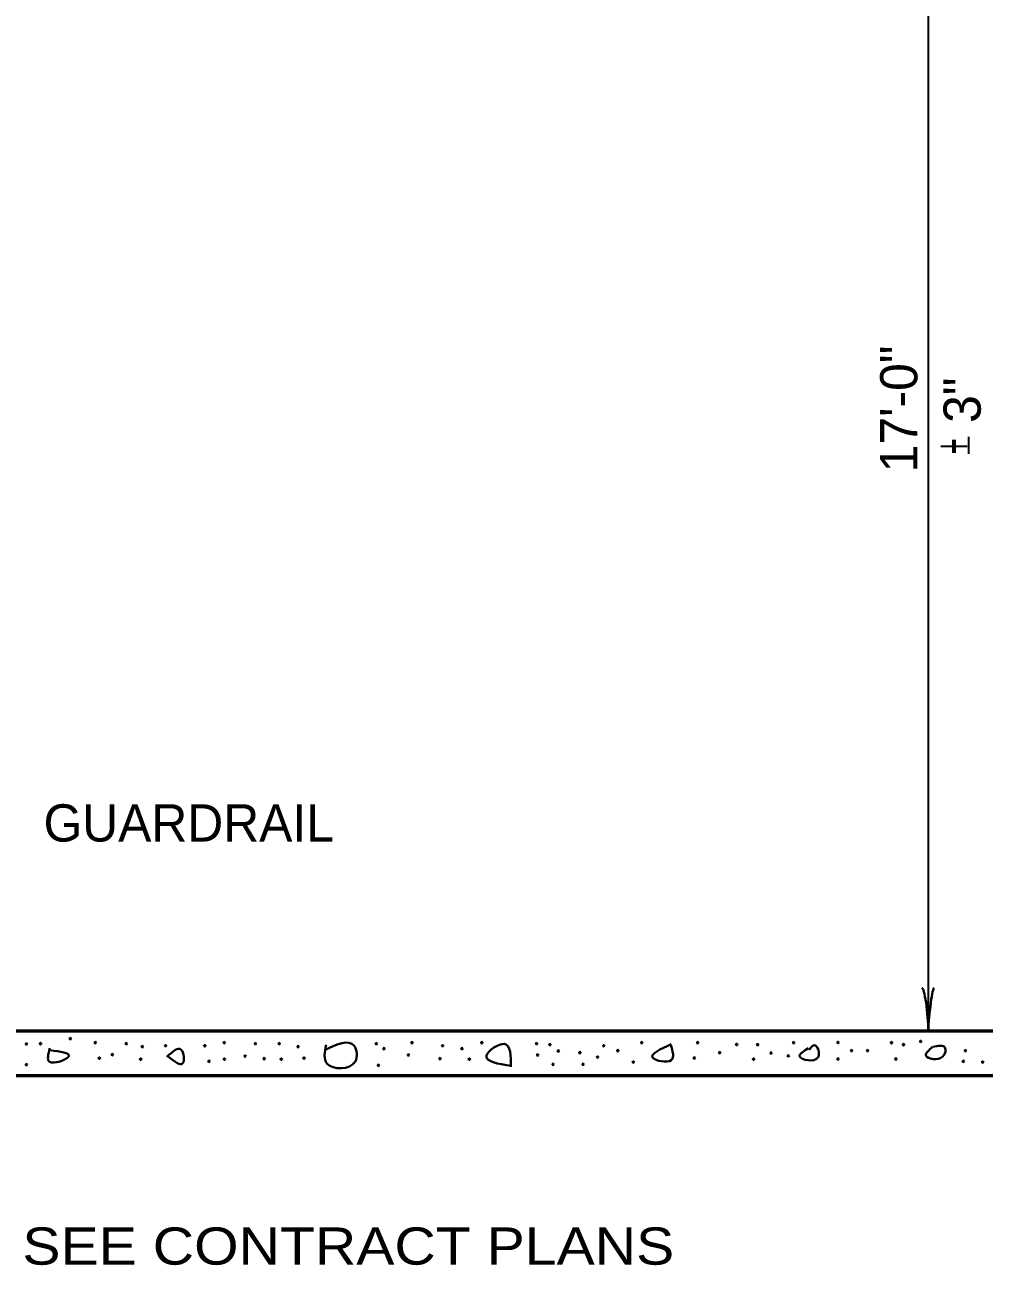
# Model space of a CAD drawing. Extents: x 12366 to 13046, y 9129 to 9570.
# Drawn here: x 12498.6 to 12563.1, y 9378.4 to 9461.7 of the extents above; entities that cross this region are included whole.
import ezdxf
from ezdxf.enums import TextEntityAlignment as Align

# ---------------------------------------------------------------- set-up
doc = ezdxf.new("R2010")
doc.units = 0
doc.layers.add('1', color=7, linetype='Continuous', lineweight=53)

msp = doc.modelspace()

# ---------------------------------------------------------------- linework, layer by layer
at = {"layer": '1', "lineweight": 35}
for p, q in [((12559.307, 9478.407), (12559.307, 9394.186)), ((12562.036, 9432.922), (12562.036, 9434.078))]:
    msp.add_line(p, q, dxfattribs=at)
at = {"layer": '1'}
for points in [[(12495.321, 9394.186), (12620.321, 9394.186), (12620.321, 9397.186), (12649.358, 9397.186)], [(12495.321, 9394.167), (12495.321, 9391.186), (12622.571, 9391.186), (12622.571, 9397.186)]]:
    msp.add_lwpolyline(points, dxfattribs=at)
at = {"layer": '1', "lineweight": 40}
for centre in [(12498.726, 9393.289), (12499.671, 9393.312), (12501.679, 9393.646), (12503.35, 9393.382), (12505.433, 9393.312), (12506.511, 9393.109), (12508.072, 9393.174), (12510.71, 9393.174), (12512.013, 9393.377), (12514.112, 9393.312), (12515.709, 9393.312), (12516.979, 9393.109), (12522.236, 9393.312), (12524.629, 9393.377), (12526.679, 9393.174), (12529.318, 9393.382), (12532.997, 9393.312), (12533.89, 9393.243), (12537.51, 9393.174), (12540.064, 9393.377), (12543.822, 9393.377), (12546.438, 9393.257), (12547.849, 9393.243), (12550.265, 9393.377), (12553.243, 9393.396), (12556.841, 9393.377), (12557.646, 9393.243), (12558.797, 9393.465), (12503.628, 9392.341), (12504.497, 9392.572), (12506.405, 9392.271), (12512.029, 9392.271), (12513.418, 9392.479), (12514.698, 9392.304), (12515.848, 9392.271), (12517.375, 9392.341), (12522.751, 9392.975), (12524.388, 9392.549), (12526.509, 9392.304), (12527.985, 9392.975), (12528.484, 9392.271), (12533.067, 9392.549), (12534.456, 9392.826), (12535.904, 9392.706), (12537.094, 9392.41), (12538.454, 9392.84), (12543.592, 9392.354), (12545.299, 9392.706), (12547.571, 9392.271), (12548.751, 9392.688), (12549.91, 9392.493), (12553.243, 9392.285), (12554.157, 9392.84), (12555.231, 9392.84), (12557.131, 9392.285), (12561.807, 9392.84), (12498.726, 9391.901), (12510.988, 9392.132), (12522.374, 9391.854), (12534.108, 9391.924), (12536.122, 9391.924), (12539.495, 9392.077), (12561.665, 9392.132), (12562.963, 9392.077)]:
    msp.add_circle(centre, 0.05, dxfattribs=at)
for centre, major_axis, ratio, start_param, end_param in [((12559.031, 9395.277), (0.156, -1.786), 0.122415, 0.896353, 3.141593), ((12559.519, 9395.307), (0.176, 1.756), 0.07063, 6.282307, 8.559703)]:
    msp.add_ellipse(centre, major_axis=major_axis, ratio=ratio, start_param=start_param, end_param=end_param, dxfattribs=at)
for points in [[(12508.155, 9392.436), (12509.128, 9392.906), (12509.229, 9392), (12508.222, 9392.469)], [(12518.858, 9393.241), (12518.926, 9391.966), (12520.805, 9392.1), (12520.737, 9393.174), (12518.791, 9392.906)], [(12531.307, 9391.815), (12529.629, 9392.52), (12530.837, 9393.292), (12531.273, 9391.748)], [(12542.044, 9393.275), (12540.802, 9392.369), (12542.044, 9392.201), (12542.01, 9393.242)], [(12551.271, 9393.007), (12550.667, 9392.47), (12551.909, 9392.403), (12551.674, 9393.208), (12551.305, 9392.906)], [(12559.593, 9393.091), (12559.156, 9392.52), (12560.297, 9392.453), (12560.431, 9393.057), (12559.626, 9393.091)], [(12500.303, 9393.006), (12500.27, 9392.1), (12501.578, 9392.469), (12500.303, 9392.872)]]:
    msp.add_spline(points, degree=3, dxfattribs=at)

# ---------------------------------------------------------------- texts
at = {"layer": '1'}
for s, p in [('17\'-0"', (12558.577, 9435.942)), ('3"', (12562.832, 9436.528))]:
    msp.add_text(s, height=2.5, rotation=90, dxfattribs=at).set_placement(p, align=Align.CENTER)
at = {"layer": '1', "width": 0.55}
msp.add_text('+', height=2.5, rotation=90, dxfattribs=at).set_placement((12562.248, 9432.896))
at = {"layer": '1'}
msp.add_text('GUARDRAIL', height=2.5, dxfattribs=at).set_placement((12499.875, 9406.887))
at = {"layer": '1', "width": 1.15}
msp.add_text('SEE CONTRACT PLANS', height=2.5, dxfattribs=at).set_placement((12520.349, 9378.472), align=Align.CENTER)

doc.saveas('drawing.dxf')
